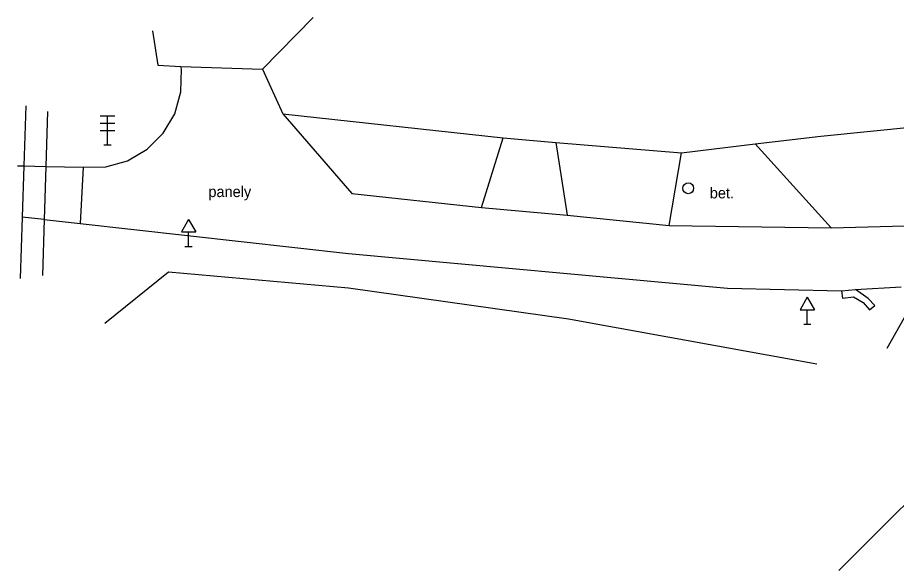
# Model space of a CAD drawing. Extents: x -762483 to -761175, y -1154655 to -1152452.
# Drawn here: x -762482.9 to -762422.2, y -1152958.9 to -1152920.7 of the extents above; entities that cross this region are included whole.
import ezdxf

# ---------------------------------------------------------------- set-up
doc = ezdxf.new("R2010")
doc.units = 0
for name, color, linetype in [('MAP_ZN_BP', 7, 'Continuous'), ('POMOC_POPIS', 7, 'Continuous'), ('ROZHRANÍ_PLOCH', 7, 'Continuous'), ('ZELEŇ', 7, 'Continuous'), ('ZN_DOPLŇKOVÉ', 7, 'Continuous')]:
    doc.layers.add(name, color=color, linetype=linetype)

msp = doc.modelspace()

# ---------------------------------------------------------------- linework, layer by layer
at = {"layer": 'MAP_ZN_BP'}
for radius in [0.375, 0.0005]:
    msp.add_circle((-762436.55, -1152932.521), radius, dxfattribs=at)
at = {"layer": 'ROZHRANÍ_PLOCH'}
for p, q in [((-762464.56, -1152927.39), (-762459.79, -1152932.89)), ((-762450.84, -1152933.85), (-762449.33, -1152929.03)), ((-762445.69, -1152929.36), (-762444.91, -1152934.38)), ((-762431.92, -1152929.45), (-762426.67, -1152935.25)), ((-762437.86, -1152935.1), (-762437.02, -1152930.07)), ((-762482.9, -1152930.97), (-762482.47, -1152930.98)), ((-762482.47, -1152930.98), (-762480.95, -1152931.01)), ((-762480.95, -1152931.01), (-762478.37, -1152931.07)), ((-762478.37, -1152931.07), (-762478.58, -1152934.96)), ((-762459.79, -1152932.89), (-762450.84, -1152933.85)), ((-762450.84, -1152933.85), (-762444.91, -1152934.38)), ((-762481.06, -1152934.68), (-762482.58, -1152934.51)), ((-762444.91, -1152934.38), (-762437.86, -1152935.1)), ((-762481.06, -1152934.68), (-762478.58, -1152934.96)), ((-762478.58, -1152934.96), (-762460.04, -1152937.03)), ((-762437.86, -1152935.1), (-762426.67, -1152935.25)), ((-762426.67, -1152935.25), (-762419.69, -1152935.07)), ((-762460.04, -1152937.03), (-762433.84, -1152939.42)), ((-762433.84, -1152939.42), (-762425.95, -1152939.61)), ((-762424.98, -1152939.52), (-762421.83, -1152939.33))]:
    msp.add_line(p, q, dxfattribs=at)
msp.add_lwpolyline([(-762478.37, -1152931.07), (-762476.8, -1152931.04), (-762475.3, -1152930.62), (-762473.95, -1152929.83), (-762472.84, -1152928.72), (-762472.04, -1152927.38), (-762471.62, -1152925.87), (-762471.58, -1152924.3), (-762471.61, -1152924.1)], dxfattribs=at)
at = {"layer": 'ZELEŇ'}
msp.add_lwpolyline([(-762476.87, -1152941.84), (-762472.46, -1152938.3), (-762460.03, -1152939.39), (-762444.83, -1152941.55), (-762427.67, -1152944.64)], dxfattribs=at)
at = {"layer": 'ZN_DOPLŇKOVÉ'}
for p, q in [((-762465.97, -1152924.3), (-762462.48, -1152920.73)), ((-762473.57, -1152921.64), (-762473.21, -1152924.02)), ((-762473.21, -1152924.02), (-762471.61, -1152924.1)), ((-762471.61, -1152924.1), (-762465.97, -1152924.3)), ((-762465.97, -1152924.3), (-762464.56, -1152927.39)), ((-762476.19, -1152927.53), (-762477.19, -1152927.53)), ((-762476.69, -1152929.53), (-762476.69, -1152927.53)), ((-762464.56, -1152927.39), (-762449.33, -1152929.03)), ((-762427.38, -1152928.93), (-762416.09, -1152927.76)), ((-762477.19, -1152928.03), (-762476.19, -1152928.03)), ((-762477.19, -1152928.53), (-762476.19, -1152928.53)), ((-762449.33, -1152929.03), (-762445.69, -1152929.36)), ((-762431.92, -1152929.45), (-762427.38, -1152928.93)), ((-762476.94, -1152929.53), (-762476.44, -1152929.53)), ((-762445.69, -1152929.36), (-762437.02, -1152930.07)), ((-762437.02, -1152930.07), (-762431.92, -1152929.45)), ((-762471.08, -1152934.674), (-762471.58, -1152935.54)), ((-762471.08, -1152934.674), (-762470.58, -1152935.54)), ((-762471.58, -1152935.54), (-762470.58, -1152935.54)), ((-762471.08, -1152936.54), (-762471.08, -1152935.54)), ((-762471.33, -1152936.54), (-762470.83, -1152936.54)), ((-762428.32, -1152940.044), (-762428.82, -1152940.91)), ((-762428.32, -1152940.044), (-762427.82, -1152940.91)), ((-762425.95, -1152939.61), (-762424.98, -1152939.52)), ((-762425.95, -1152939.61), (-762425.88, -1152940.11)), ((-762425.88, -1152940.11), (-762425.14, -1152940.01)), ((-762425.14, -1152940.01), (-762424.46, -1152940.42)), ((-762424.11, -1152940.13), (-762424.98, -1152939.52)), ((-762424.46, -1152940.42), (-762424.03, -1152940.92)), ((-762423.66, -1152940.61), (-762424.11, -1152940.13)), ((-762424.03, -1152940.92), (-762423.66, -1152940.61)), ((-762428.82, -1152940.91), (-762427.82, -1152940.91)), ((-762428.32, -1152941.91), (-762428.32, -1152940.91)), ((-762428.57, -1152941.91), (-762428.07, -1152941.91))]:
    msp.add_line(p, q, dxfattribs=at)
for points in [[(-762482.34, -1152926.82), (-762482.47, -1152930.98)], [(-762480.84, -1152927.22), (-762480.95, -1152931.01)], [(-762426.15, -1152958.92), (-762408.78, -1152941.61), (-762402.44, -1152935.67), (-762395.35, -1152929.2)], [(-762482.47, -1152930.98), (-762482.58, -1152934.51)], [(-762480.95, -1152931.01), (-762481.06, -1152934.68)], [(-762482.58, -1152934.51), (-762482.72, -1152938.76)], [(-762481.06, -1152934.68), (-762481.17, -1152938.55)], [(-762420.44, -1152939.35), (-762422.82, -1152943.58)]]:
    msp.add_lwpolyline(points, dxfattribs=at)

# ---------------------------------------------------------------- texts
at = {"layer": 'POMOC_POPIS'}
for s, p in [('panely', (-762469.71, -1152933.13)), ('bet.', (-762435.06, -1152933.22))]:
    msp.add_text(s, height=0.75, dxfattribs=at).set_placement(p)

doc.saveas('drawing.dxf')
